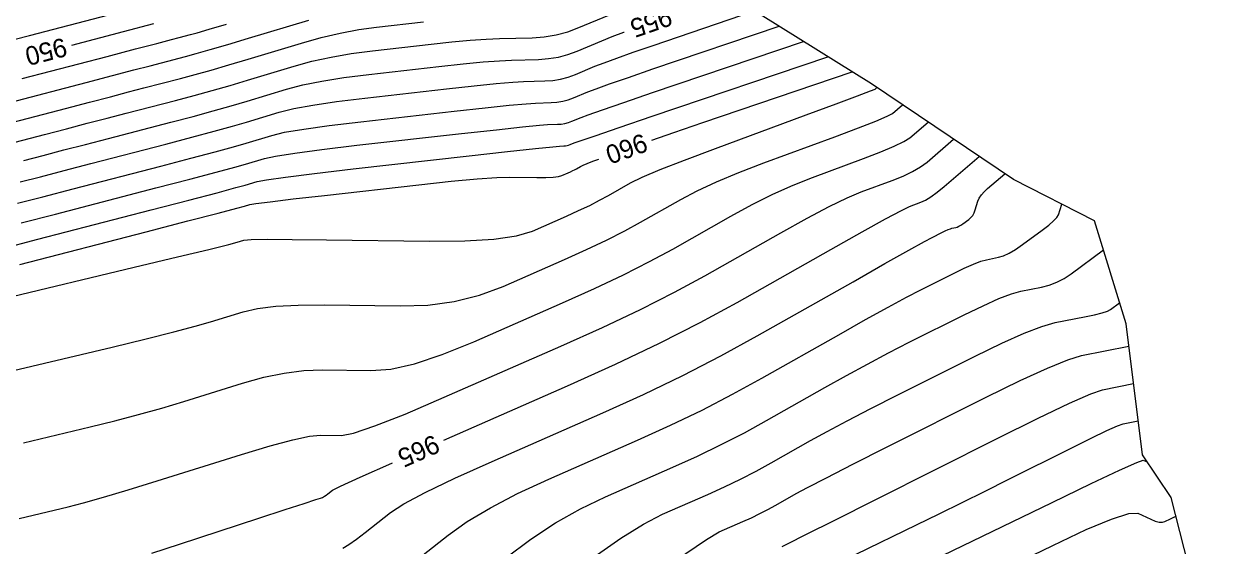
# Model space of a CAD drawing. Extents: x 2175772 to 2185556, y 721391 to 722853.
# Drawn here: x 2178980.9 to 2179161.1, y 722020.3 to 722098.3 of the extents above; entities that cross this region are included whole.
import ezdxf

# ---------------------------------------------------------------- set-up
doc = ezdxf.new("R2010")
doc.units = 0
for name, color, linetype in [('DT_X_Contour_Major', 7, 'Continuous'), ('DT_X_Contour_Minor', 7, 'Continuous'), ('DT_X_TIN_Hull', 7, 'Continuous')]:
    doc.layers.add(name, color=color, linetype=linetype)

msp = doc.modelspace()

# ---------------------------------------------------------------- linework, layer by layer
at = {"layer": 'DT_X_Contour_Major'}
for points in [[(2178988.05, 722095.21), (2178995.76, 722097.23), (2179000.3, 722098.42)], [(2178980.85, 722077.95), (2178983.77, 722078.72), (2178986.85, 722079.52), (2178990.1, 722080.36), (2178993.51, 722081.25), (2179002.83, 722083.67), (2179006.16, 722084.54), (2179009.18, 722085.36), (2179011.87, 722086.12), (2179014.24, 722086.82), (2179020.15, 722088.6), (2179022.58, 722089.24), (2179025.44, 722089.82), (2179028.72, 722090.35), (2179032.44, 722090.82), (2179042.91, 722092), (2179046.54, 722092.39), (2179049.56, 722092.68), (2179051.98, 722092.87), (2179053.8, 722092.96), (2179057.83, 722093.07), (2179059.33, 722093.18), (2179060.79, 722093.42), (2179062.22, 722093.8), (2179063.62, 722094.31), (2179067.3, 722095.85), (2179068.82, 722096.46), (2179070.61, 722097.14), (2179070.64, 722097.15)], [(2179074.75, 722081.01), (2179078.06, 722082.14), (2179082.4, 722083.62), (2179104.75, 722091.19)], [(2178980.28, 722062.4), (2178999.15, 722067.29), (2179005.37, 722068.91), (2179009.9, 722070.09), (2179012.73, 722070.83), (2179013.87, 722071.14), (2179014.63, 722071.37), (2179015.54, 722071.51), (2179017.71, 722071.79), (2179021.13, 722072.2), (2179025.81, 722072.73), (2179039.95, 722074.32), (2179044.78, 722074.84), (2179048.66, 722075.2), (2179051.59, 722075.41), (2179053.56, 722075.47), (2179057.57, 722075.42), (2179058.93, 722075.42), (2179060.01, 722075.46), (2179060.8, 722075.56), (2179061.31, 722075.69), (2179062.28, 722076.12), (2179062.63, 722076.28), (2179062.95, 722076.43), (2179063.23, 722076.57), (2179063.49, 722076.71), (2179064.12, 722077.07), (2179064.48, 722077.24), (2179065.09, 722077.5), (2179065.95, 722077.83), (2179066.85, 722078.17)], [(2179043.67, 722036.16), (2179062.18, 722044.28), (2179069.33, 722047.5), (2179075.93, 722050.65), (2179082, 722053.73), (2179087.52, 722056.73), (2179101.54, 722064.66), (2179106.22, 722067.29), (2179109.74, 722069.24), (2179112.11, 722070.5), (2179113.32, 722071.08), (2179115.01, 722071.7), (2179115.7, 722072.02), (2179116.52, 722072.53), (2179117.45, 722073.22), (2179118.51, 722074.08), (2179123.73, 722078.55)], [(2179057.81, 722002.05), (2179070.25, 722011.85), (2179075.64, 722016.04), (2179079.86, 722019.2), (2179082.93, 722021.32), (2179084.84, 722022.42), (2179088.37, 722023.97), (2179089.67, 722024.56), (2179090.93, 722025.17), (2179092.14, 722025.79), (2179093.31, 722026.43), (2179096.37, 722028.16), (2179098.07, 722029.08), (2179100.89, 722030.54), (2179104.82, 722032.54), (2179109.86, 722035.08), (2179124.78, 722042.57), (2179129.87, 722045.06), (2179133.93, 722046.93), (2179136.98, 722048.17), (2179139.01, 722048.78), (2179146.11, 722050.18)], [(2179000.01, 722019.25), (2179004.12, 722020.59), (2179016.02, 722024.48), (2179019.95, 722025.76), (2179022.78, 722026.69), (2179024.53, 722027.26), (2179025.2, 722027.48), (2179025.52, 722027.6), (2179025.66, 722027.66), (2179025.84, 722027.77), (2179026.06, 722027.92), (2179026.31, 722028.11), (2179027.03, 722028.68), (2179028.19, 722029.27), (2179031.14, 722030.62), (2179035.88, 722032.73), (2179035.98, 722032.78)]]:
    msp.add_lwpolyline(points, dxfattribs=at)
at = {"layer": 'DT_X_Contour_Minor'}
for points in [[(2178975.11, 722079.53), (2178983.97, 722081.84), (2178987.22, 722082.69), (2178990.33, 722083.51), (2178993.31, 722084.28), (2178996.16, 722085.02), (2179003.56, 722086.94), (2179006.32, 722087.67), (2179009.03, 722088.42), (2179011.7, 722089.18), (2179014.32, 722089.95), (2179021.26, 722092.05), (2179023.94, 722092.78), (2179026.8, 722093.41), (2179029.82, 722093.93), (2179033.02, 722094.35), (2179041.78, 722095.34), (2179044.88, 722095.67), (2179047.62, 722095.92), (2179049.99, 722096.08), (2179052, 722096.17), (2179056.88, 722096.31), (2179058.69, 722096.44), (2179060.46, 722096.73), (2179062.19, 722097.19), (2179063.88, 722097.81), (2179068.34, 722099.67)], [(2178977.44, 722095.56), (2178981.68, 722096.62), (2178993.56, 722099.73)], [(2178980.33, 722074.74), (2178983.37, 722075.53), (2178986.89, 722076.45), (2178990.87, 722077.48), (2179002.09, 722080.39), (2179006, 722081.42), (2179009.32, 722082.31), (2179012.04, 722083.06), (2179014.17, 722083.68), (2179019.05, 722085.15), (2179021.22, 722085.7), (2179024.08, 722086.24), (2179027.62, 722086.77), (2179031.85, 722087.28), (2179044.05, 722088.66), (2179048.2, 722089.11), (2179051.51, 722089.44), (2179053.97, 722089.66), (2179055.59, 722089.75), (2179058.78, 722089.84), (2179059.96, 722089.92), (2179061.12, 722090.11), (2179062.25, 722090.41), (2179063.35, 722090.81), (2179066.26, 722092.03), (2179067.62, 722092.57), (2179069.53, 722093.27), (2179071.97, 722094.13), (2179074.96, 722095.15), (2179090.15, 722100.3)], [(2178976.94, 722083.08), (2178987.08, 722085.73), (2178990.66, 722086.67), (2178993.81, 722087.49), (2178996.53, 722088.2), (2178998.8, 722088.79), (2179004.3, 722090.22), (2179006.48, 722090.8), (2179008.88, 722091.47), (2179011.52, 722092.23), (2179014.4, 722093.09), (2179022.36, 722095.49), (2179025.3, 722096.32), (2179028.16, 722096.99), (2179030.93, 722097.52), (2179033.61, 722097.89), (2179040.64, 722098.68)], [(2178978.76, 722086.63), (2178990.19, 722089.62), (2178994.11, 722090.65), (2178997.29, 722091.48), (2178999.74, 722092.12), (2179001.45, 722092.56), (2179005.04, 722093.49), (2179006.63, 722093.92), (2179008.74, 722094.52), (2179011.35, 722095.29), (2179014.47, 722096.23), (2179023.46, 722098.94)], [(2178979.9, 722071.55), (2178983.68, 722072.53), (2178988.22, 722073.71), (2179001.36, 722077.12), (2179005.85, 722078.29), (2179009.47, 722079.25), (2179012.22, 722080), (2179014.09, 722080.54), (2179017.94, 722081.71), (2179019.86, 722082.16), (2179022.72, 722082.65), (2179026.52, 722083.18), (2179031.27, 722083.75), (2179045.19, 722085.31), (2179049.87, 722085.83), (2179053.46, 722086.21), (2179055.97, 722086.44), (2179057.39, 722086.54), (2179059.73, 722086.6), (2179060.59, 722086.66), (2179061.44, 722086.8), (2179062.27, 722087.02), (2179063.08, 722087.32), (2179065.22, 722088.21), (2179066.43, 722088.68), (2179068.45, 722089.4), (2179071.28, 722090.38), (2179074.92, 722091.63), (2179093.8, 722098.02)], [(2178980.59, 722090.19), (2178993.3, 722093.51), (2178997.56, 722094.62), (2179000.77, 722095.46), (2179002.95, 722096.03), (2179004.1, 722096.33), (2179005.77, 722096.77), (2179006.79, 722097.05), (2179008.59, 722097.58), (2179011.18, 722098.35)], [(2178980.46, 722068.61), (2178985.57, 722069.94), (2179000.62, 722073.84), (2179005.69, 722075.16), (2179009.61, 722076.2), (2179012.39, 722076.95), (2179014.02, 722077.41), (2179016.84, 722078.26), (2179018.5, 722078.62), (2179021.36, 722079.07), (2179025.42, 722079.6), (2179030.68, 722080.22), (2179046.33, 722081.97), (2179051.53, 722082.55), (2179055.41, 722082.97), (2179057.96, 722083.23), (2179059.18, 722083.32), (2179060.67, 722083.36), (2179061.23, 722083.4), (2179061.77, 722083.49), (2179062.3, 722083.63), (2179062.82, 722083.82), (2179064.18, 722084.39), (2179065.23, 722084.78), (2179067.37, 722085.53), (2179070.58, 722086.64), (2179074.88, 722088.1), (2179097.45, 722095.74)], [(2178977.25, 722064.69), (2178982.93, 722066.17), (2178999.88, 722070.57), (2179005.53, 722072.04), (2179009.76, 722073.14), (2179012.56, 722073.89), (2179013.94, 722074.27), (2179015.73, 722074.81), (2179017.13, 722075.08), (2179020, 722075.48), (2179024.32, 722076.01), (2179030.1, 722076.68), (2179047.47, 722078.63), (2179053.2, 722079.27), (2179057.36, 722079.73), (2179059.95, 722080.01), (2179060.98, 722080.11), (2179061.62, 722080.13), (2179061.86, 722080.14), (2179062.1, 722080.18), (2179062.33, 722080.24), (2179062.55, 722080.33), (2179063.14, 722080.57), (2179064.04, 722080.89), (2179066.29, 722081.66), (2179069.89, 722082.89), (2179074.84, 722084.57), (2179101.1, 722093.46)], [(2178977.85, 722057.34), (2178997.37, 722061.99), (2179003.83, 722063.53), (2179008.54, 722064.67), (2179011.53, 722065.4), (2179012.77, 722065.72), (2179013.78, 722066.03), (2179014.83, 722066.12), (2179017.24, 722066.17), (2179021, 722066.16), (2179026.11, 722066.11), (2179041.53, 722065.9), (2179046.83, 722065.93), (2179051.16, 722066.19), (2179054.52, 722066.69), (2179056.91, 722067.41), (2179062, 722069.64), (2179063.82, 722070.46), (2179065.48, 722071.24), (2179066.97, 722072), (2179068.29, 722072.72), (2179071.6, 722074.59), (2179073.33, 722075.44), (2179076.01, 722076.58), (2179079.66, 722078.02), (2179084.28, 722079.75), (2179097.86, 722084.76), (2179102.33, 722086.41), (2179105.53, 722087.61), (2179107.48, 722088.34), (2179108.17, 722088.62), (2179108.43, 722088.84)], [(2178979.33, 722046.54), (2178994.07, 722050.06), (2178999.14, 722051.28), (2179003.28, 722052.32), (2179006.5, 722053.17), (2179008.79, 722053.83), (2179013.66, 722055.35), (2179015.79, 722055.84), (2179018.52, 722056.18), (2179021.86, 722056.35), (2179025.81, 722056.37), (2179037.13, 722056.22), (2179041.28, 722056.35), (2179045.23, 722056.89), (2179048.98, 722057.81), (2179052.52, 722059.12), (2179061.72, 722063.16), (2179065.01, 722064.64), (2179068.01, 722066.06), (2179070.71, 722067.42), (2179073.1, 722068.72), (2179079.09, 722072.11), (2179081.55, 722073.4), (2179084.45, 722074.75), (2179087.77, 722076.14), (2179091.54, 722077.58), (2179102.15, 722081.5), (2179105.67, 722082.82), (2179108.28, 722083.84), (2179109.97, 722084.56), (2179110.75, 722084.98), (2179112.25, 722086.27)], [(2178980.8, 722035.75), (2178990.77, 722038.13), (2178994.46, 722039.03), (2178998.02, 722039.97), (2179001.47, 722040.95), (2179004.8, 722041.95), (2179013.54, 722044.67), (2179016.74, 722045.56), (2179019.81, 722046.18), (2179022.73, 722046.54), (2179025.51, 722046.64), (2179032.74, 722046.54), (2179035.73, 722046.78), (2179039.29, 722047.58), (2179043.43, 722048.93), (2179048.13, 722050.84), (2179061.43, 722056.67), (2179066.21, 722058.82), (2179070.54, 722060.87), (2179074.44, 722062.84), (2179077.91, 722064.72), (2179086.57, 722069.63), (2179089.77, 722071.37), (2179092.88, 722072.91), (2179095.89, 722074.26), (2179098.8, 722075.41), (2179106.44, 722078.23), (2179109.02, 722079.22), (2179111.03, 722080.07), (2179112.47, 722080.78), (2179113.34, 722081.35), (2179116.08, 722083.7)], [(2178980.16, 722024.44), (2178982.27, 722024.95), (2178987.47, 722026.19), (2178989.77, 722026.78), (2178992.76, 722027.63), (2178996.44, 722028.72), (2179000.82, 722030.07), (2179013.42, 722033.99), (2179017.7, 722035.28), (2179021.09, 722036.19), (2179023.59, 722036.73), (2179025.21, 722036.9), (2179028.34, 722036.86), (2179030.18, 722037.2), (2179033.36, 722038.27), (2179037.88, 722040.05), (2179043.74, 722042.55), (2179061.15, 722050.19), (2179067.4, 722053), (2179073.07, 722055.69), (2179078.18, 722058.27), (2179082.72, 722060.73), (2179094.06, 722067.14), (2179098, 722069.33), (2179101.31, 722071.08), (2179104, 722072.38), (2179106.06, 722073.25), (2179110.72, 722074.97), (2179112.36, 722075.62), (2179113.77, 722076.3), (2179114.96, 722077), (2179115.93, 722077.72), (2179119.9, 722081.12)], [(2179028.55, 722020.01), (2179029.48, 722020.57), (2179030.6, 722021.35), (2179031.91, 722022.35), (2179035.67, 722025.31), (2179037.68, 722026.62), (2179040.89, 722028.34), (2179045.29, 722030.45), (2179050.89, 722032.97), (2179067.42, 722040.22), (2179073.51, 722042.98), (2179079.4, 722045.82), (2179085.08, 722048.73), (2179090.55, 722051.73), (2179104.87, 722059.83), (2179109.64, 722062.53), (2179113.2, 722064.53), (2179115.56, 722065.84), (2179116.7, 722066.46), (2179118.16, 722067.19), (2179118.66, 722067.43), (2179119.08, 722067.62), (2179119.42, 722067.75), (2179119.66, 722067.82), (2179120.22, 722067.92), (2179120.44, 722067.99), (2179120.7, 722068.11), (2179120.98, 722068.28), (2179121.3, 722068.5), (2179122.18, 722069.15), (2179122.49, 722069.42), (2179122.76, 722069.75), (2179122.97, 722070.14), (2179123.15, 722070.59), (2179123.55, 722071.86), (2179123.75, 722072.33), (2179124.05, 722072.81), (2179124.46, 722073.28), (2179124.96, 722073.76), (2179127.55, 722075.98)], [(2179037.52, 722016.59), (2179044.32, 722021.95), (2179047.17, 722023.98), (2179050.63, 722026.05), (2179054.7, 722028.17), (2179059.38, 722030.33), (2179072.65, 722036.16), (2179077.55, 722038.37), (2179082.28, 722040.65), (2179086.85, 722043), (2179091.24, 722045.41), (2179102.75, 722051.91), (2179106.75, 722054.16), (2179110.12, 722056.03), (2179112.87, 722057.51), (2179114.99, 722058.61), (2179119.81, 722061.03), (2179121.48, 722061.84), (2179122.87, 722062.46), (2179123.98, 722062.89), (2179124.81, 722063.12), (2179126.64, 722063.48), (2179127.38, 722063.7), (2179128.22, 722064.09), (2179129.17, 722064.64), (2179130.22, 722065.37), (2179133.15, 722067.54), (2179134.13, 722068.29), (2179134.85, 722068.92), (2179135.33, 722069.44), (2179135.57, 722069.84), (2179136.07, 722071.44)], [(2179052.96, 722018.58), (2179056.66, 722021.33), (2179060.38, 722023.77), (2179064.11, 722025.89), (2179067.86, 722027.7), (2179077.89, 722032.09), (2179081.59, 722033.77), (2179085.16, 722035.49), (2179088.61, 722037.26), (2179091.93, 722039.08), (2179100.62, 722044), (2179103.86, 722045.8), (2179107.05, 722047.53), (2179110.19, 722049.19), (2179113.28, 722050.77), (2179121.47, 722054.88), (2179124.3, 722056.25), (2179126.66, 722057.3), (2179128.54, 722058.02), (2179129.95, 722058.42), (2179133.06, 722059.03), (2179134.21, 722059.33), (2179135.33, 722059.76), (2179136.42, 722060.32), (2179137.47, 722061.02), (2179142.31, 722064.59)], [(2179066.15, 722018.69), (2179070.12, 722021.48), (2179073.52, 722023.61), (2179076.35, 722025.06), (2179083.13, 722028.03), (2179085.63, 722029.16), (2179088.05, 722030.33), (2179090.38, 722031.53), (2179092.62, 722032.76), (2179098.5, 722036.08), (2179100.97, 722037.44), (2179103.97, 722039.04), (2179107.5, 722040.86), (2179111.57, 722042.92), (2179123.12, 722048.72), (2179127.12, 722050.67), (2179130.45, 722052.15), (2179133.1, 722053.16), (2179135.09, 722053.72), (2179139.48, 722054.58), (2179140.96, 722054.89), (2179142.1, 722055.18), (2179142.9, 722055.44), (2179143.37, 722055.66), (2179144.73, 722056.67)], [(2179094.24, 722020.24), (2179095.18, 722020.72), (2179097.81, 722022.04), (2179102.13, 722024.21), (2179108.15, 722027.23), (2179126.43, 722036.41), (2179132.56, 722039.45), (2179137.22, 722041.67), (2179140.42, 722043.09), (2179142.15, 722043.69), (2179146.81, 722044.61)], [(2179105.32, 722019.11), (2179114.35, 722023.48), (2179117.74, 722025.13), (2179121.16, 722026.81), (2179124.61, 722028.52), (2179128.08, 722030.25), (2179137.37, 722034.91), (2179140.47, 722036.46), (2179142.83, 722037.58), (2179144.43, 722038.3), (2179145.28, 722038.6), (2179147.51, 722039.03)], [(2179116.82, 722018.21), (2179134.62, 722026.83), (2179140.48, 722029.66), (2179144.7, 722031.65), (2179147.28, 722032.83), (2179148.24, 722033.18), (2179148.85, 722032.89)], [(2179119.67, 722013.13), (2179134.72, 722020.42), (2179139.75, 722022.77), (2179143.54, 722024.35), (2179146.12, 722025.17), (2179147.46, 722025.22), (2179149.39, 722024.33), (2179150.07, 722024.06), (2179150.64, 722023.91), (2179151.12, 722023.88), (2179151.49, 722023.98), (2179152.35, 722024.4), (2179152.63, 722024.54), (2179152.84, 722024.64), (2179152.98, 722024.7), (2179153.04, 722024.73), (2179153.15, 722024.79)]]:
    msp.add_lwpolyline(points, dxfattribs=at)
at = {"layer": 'DT_X_TIN_Hull'}
msp.add_lwpolyline([(2179161.43, 721992.4), (2179152.44, 722027.56), (2179148.14, 722033.95), (2179145.69, 722053.55), (2179140.98, 722068.94), (2179128.84, 722075.11), (2179107.62, 722089.39), (2179075.12, 722109.69)], dxfattribs=at)

# ---------------------------------------------------------------- texts
at = {"layer": 'DT_X_Contour_Major'}
for s, rotation, p in [('955', 199.0625, (2179077.18, 722100.92)), ('950', 194.5398, (2178986.86, 722096.34)), ('960', 199.7652, (2179073.47, 722082.07)), ('965', 203.7536, (2179042.21, 722037.05))]:
    msp.add_text(s, height=2.8, rotation=rotation, dxfattribs=at).set_placement(p)

doc.saveas('drawing.dxf')
